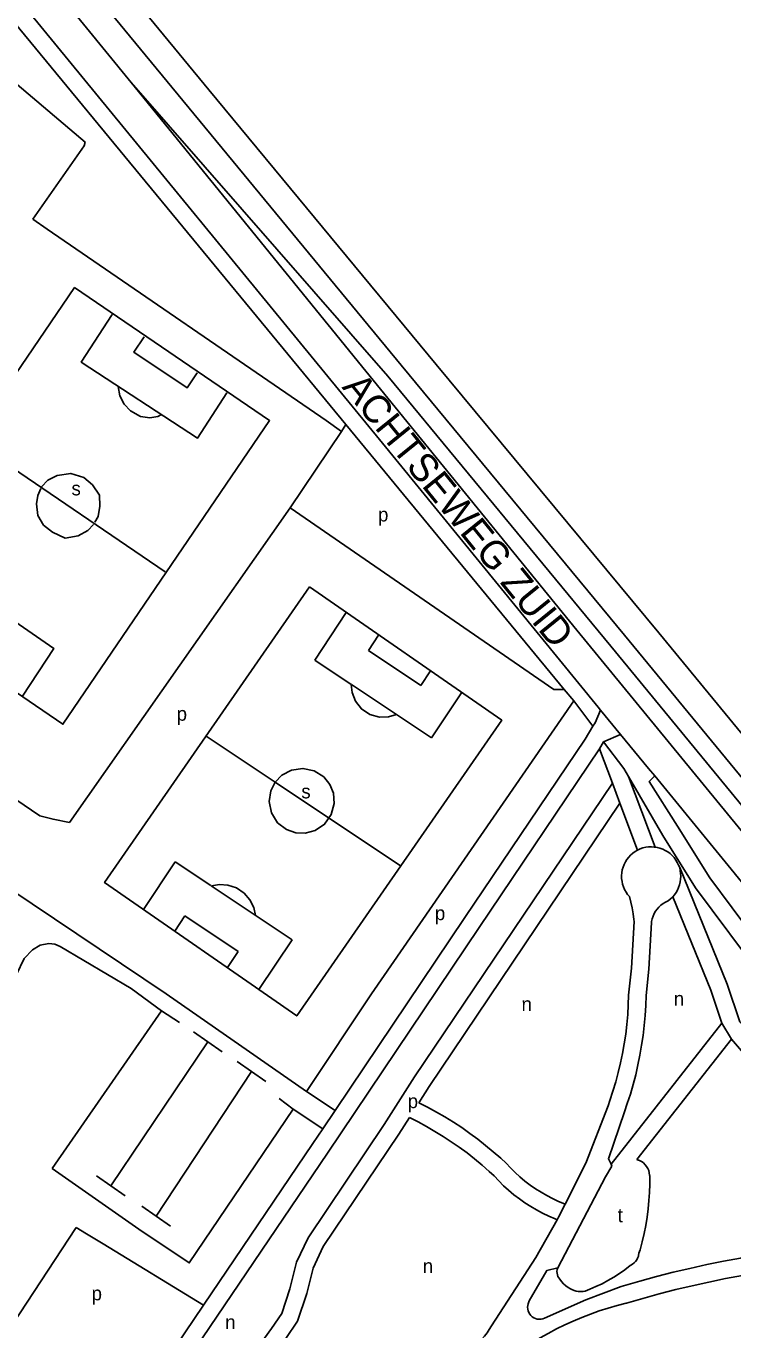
# Model space of a CAD drawing. Extents: x 157155 to 159285, y 385001 to 386651.
# Drawn here: x 158665.4 to 158867.8, y 385603.8 to 385977 of the extents above; entities that cross this region are included whole.
import ezdxf

# ---------------------------------------------------------------- set-up
doc = ezdxf.new("R2010")
doc.units = 0
for name, color, linetype in [('BLT_Basislijn', 7, 'Continuous'), ('BLT_Centroide', 7, 'Continuous'), ('BLT_Spoorlijn', 7, 'Continuous'), ('BLT_Straatnaam_hoofdweg', 7, 'Continuous'), ('BLT_Vlakafsluiter', 7, 'Continuous')]:
    doc.layers.add(name, color=color, linetype=linetype)

msp = doc.modelspace()

# ---------------------------------------------------------------- linework, layer by layer
at = {"layer": 'BLT_Basislijn'}
for p, q in [((158491.12, 386194.55), (158766.6, 385858.7)), ((158633.61, 386036.53), (158695.48, 385960.83)), ((158695.48, 385960.83), (158762.67, 385878.23)), ((158671.44, 385918.9), (158667.29, 385921.7)), ((158671.44, 385918.9), (158751.28, 385864.08)), ((158762.67, 385878.23), (158823.13, 385804.1)), ((158755.67, 385860.96), (158751.28, 385864.08)), ((158755.67, 385860.96), (158756.98, 385862.92)), ((158756.98, 385862.92), (158819.48, 385787.09)), ((158649.78, 385858.51), (158705.22, 385820.8)), ((158755.67, 385860.96), (158741.05, 385839.1)), ((158766.6, 385858.7), (158829.23, 385782.05)), ((158677.75, 385749.03), (158741.05, 385839.1)), ((158757.09, 385809.09), (158748.05, 385795.53)), ((158766.35, 385802.67), (158763.42, 385798.27)), ((158823.13, 385804.1), (158882.02, 385732.32)), ((158778.42, 385788.26), (158763.42, 385798.27)), ((158758.5, 385788.56), (158748.05, 385795.53)), ((158781.17, 385792.39), (158778.42, 385788.26)), ((158781.49, 385773.22), (158758.57, 385788.51)), ((158822.23, 385783.87), (158819.48, 385787.09)), ((158790.13, 385786.18), (158781.49, 385773.22)), ((158827.73, 385776.56), (158822.23, 385783.87)), ((158825.5, 385772.91), (158827.73, 385776.56)), ((158736.69, 385760.59), (158716.98, 385773.74)), ((158825.5, 385772.91), (158791.02, 385721.78)), ((158829.63, 385770.09), (158830.8, 385772.08)), ((158830.8, 385772.08), (158835.67, 385774.18)), ((158835.67, 385774.18), (158843.65, 385764.52)), ((158829.63, 385770.09), (158795.16, 385718.98)), ((158829.63, 385770.09), (158833.31, 385760.28)), ((158845.43, 385762.34), (158843.65, 385764.52)), ((158772.64, 385736.61), (158736.74, 385760.56)), ((158833.31, 385760.28), (158835.47, 385754.53)), ((158837.94, 385762.18), (158845.53, 385741.97)), ((158847.74, 385745.32), (158837.94, 385762.18)), ((158913.32, 385679.35), (158845.43, 385762.34)), ((158835.47, 385754.53), (158840.52, 385741.1)), ((158708.1, 385737.76), (158699.01, 385724.13)), ((158718.32, 385730.94), (158708.1, 385737.76)), ((158741.55, 385715.46), (158718.4, 385730.89)), ((158710.83, 385722.28), (158707.94, 385717.95)), ((158726.13, 385712.07), (158710.83, 385722.28)), ((158791.02, 385721.78), (158753.86, 385666.54)), ((158838.75, 385707.32), (158839.52, 385720.68)), ((158843.74, 385707.03), (158844.52, 385720.39)), ((158741.55, 385715.46), (158732.05, 385701.22)), ((158795.16, 385718.98), (158751.68, 385654.34)), ((158726.13, 385712.07), (158723.06, 385707.46)), ((158838.75, 385707.32), (158837.97, 385699.61)), ((158843.74, 385707.03), (158842.97, 385699.51)), ((158704.11, 385695.1), (158709.26, 385691.79)), ((158864.68, 385691.6), (158832.93, 385651.18)), ((158867.44, 385687.03), (158864.68, 385691.6)), ((158717.46, 385686.21), (158689.61, 385644.99)), ((158717.46, 385686.21), (158713.35, 385689.06)), ((158717.46, 385686.21), (158721.57, 385683.37)), ((158867.44, 385687.03), (158840.34, 385652.51)), ((158729.94, 385677.77), (158725.83, 385680.62)), ((158702.58, 385636.3), (158729.94, 385677.77)), ((158729.94, 385677.77), (158734.05, 385674.92)), ((158753.86, 385666.54), (158745.66, 385672.03)), ((158741.9, 385666.99), (158737.9, 385669.99)), ((158750.32, 385661.28), (158741.9, 385666.99)), ((158753.86, 385666.54), (158750.32, 385661.28)), ((158750.32, 385661.28), (158747.52, 385657.11)), ((158747.52, 385657.11), (158716.17, 385610.87)), ((158751.68, 385654.34), (158702.89, 385582.36)), ((158833.18, 385650.63), (158831.35, 385647.58)), ((158832.93, 385651.18), (158833.18, 385650.63)), ((158842.25, 385651.56), (158842.73, 385651.05)), ((158689.61, 385644.99), (158685.5, 385647.84)), ((158689.61, 385644.99), (158693.72, 385642.15)), ((158817.65, 385621.49), (158831.35, 385647.58)), ((158702.58, 385636.3), (158698.47, 385639.15)), ((158702.58, 385636.3), (158706.69, 385633.45)), ((158679.75, 385633.1), (158682.68, 385631.31)), ((158682.68, 385631.31), (158687.43, 385628.41)), ((158687.43, 385628.41), (158716.17, 385610.87)), ((158840.93, 385625.7), (158840.79, 385625.04)), ((158716.17, 385610.87), (158702.45, 385590.64))]:
    msp.add_line(p, q, dxfattribs=at)
for points in [[(158522.06, 386149.41), (158522.79, 386148.46), (158651.38, 385990.95), (158756.98, 385862.92)], [(158667.29, 385921.7), (158682.04, 385942.77), (158682.27, 385943.78), (158605.54, 386008.81)], [(158695.48, 385960.83), (158769, 385876.77), (158832.9, 385799.5)], [(158690.04, 385894.47), (158681.14, 385880.83), (158714.49, 385859.08), (158722.9, 385871.98)], [(158699.16, 385888.05), (158696.23, 385883.65), (158711.53, 385873.46), (158714.39, 385877.77)], [(158691.74, 385873.79), (158692.18, 385871.14), (158693.5, 385868.82), (158695.27, 385866.84), (158698.1, 385865.25), (158700.82, 385864.85), (158703.14, 385865.22), (158704.13, 385865.77)], [(158669.8, 385845.15), (158671.6, 385847.02), (158674.31, 385848.31), (158678.17, 385848.96), (158681.9, 385847.8), (158684.35, 385845.67), (158686.4, 385842.77), (158686.53, 385839.61), (158685.97, 385836.57), (158685.05, 385834.95)], [(158669.57, 385844.63), (158668.69, 385842.61), (158668.39, 385840.29), (158668.72, 385836.94), (158670.37, 385834.16), (158672.94, 385832.09), (158676.55, 385830.42), (158680.28, 385831.06), (158683.05, 385832.61), (158684.65, 385834.37)], [(158741.05, 385839.1), (158816.53, 385787.07), (158819.48, 385787.09)], [(158631.35, 385807.94), (158640.63, 385821.39), (158673.35, 385798.82), (158664.31, 385785.2)], [(158832.9, 385799.5), (158892.09, 385727.58), (158939.39, 385669.9)], [(158758.53, 385788.54), (158758.75, 385786.19), (158759.7, 385783.74), (158761.44, 385781.52), (158763.85, 385779.92), (158766.56, 385779.16), (158769.19, 385779.23), (158771.44, 385779.93)], [(158822.23, 385783.87), (158764.28, 385700), (158745.66, 385672.03)], [(158827.73, 385776.56), (158828.35, 385777.57), (158829.9, 385781.15)], [(158829.9, 385781.15), (158829.23, 385782.05)], [(158837.94, 385762.18), (158836.58, 385764.52), (158830.8, 385772.08)], [(158669.25, 385750.95), (158644.07, 385768.05), (158642.98, 385768.9), (158641.27, 385766.41)], [(158736.71, 385760.56), (158735.48, 385758.11), (158735.02, 385755.06), (158735.65, 385751.8), (158737.42, 385748.95), (158739.92, 385746.98), (158742.62, 385746.03), (158745.27, 385745.92), (158748.15, 385746.69), (158750.85, 385748.52), (158752.8, 385751.27), (158753.63, 385754.43), (158753.4, 385757.4), (158752.41, 385759.86), (158750.61, 385762.09), (158747.93, 385763.8), (158744.65, 385764.51), (158741.36, 385764.03), (158738.64, 385762.57), (158736.74, 385760.6)], [(158833.31, 385760.28), (158776.66, 385676.22), (158767.96, 385662.54), (158746.13, 385630.09), (158742.84, 385623.16), (158740.94, 385615.55), (158738.59, 385608.5), (158735.7, 385604.17), (158732.44, 385599.72), (158725.45, 385593.04)], [(158851.99, 385747.97), (158843.88, 385760.79), (158845.43, 385762.34)], [(158835.47, 385754.53), (158780.85, 385673.48), (158777.85, 385668.77)], [(158669.25, 385750.95), (158673.11, 385749.93), (158677.75, 385749.03)], [(158847.74, 385745.32), (158857.12, 385730.31), (158876.46, 385704.4), (158878.49, 385701.82)], [(158851.99, 385747.97), (158861.25, 385733.14), (158880.43, 385707.44), (158897.54, 385685.66), (158918.07, 385656.71), (158928.84, 385641.73)], [(158845.53, 385741.97), (158845.33, 385742), (158844.51, 385742.05), (158843.69, 385742.02), (158842.87, 385741.91), (158842.07, 385741.72), (158841.29, 385741.45), (158840.52, 385741.1)], [(158852.61, 385736.09), (158852.25, 385736.84), (158851.9, 385737.58), (158851.48, 385738.28), (158850.98, 385738.95), (158850.43, 385739.56), (158849.82, 385740.11), (158849.16, 385740.6), (158848.46, 385741.03), (158847.72, 385741.39), (158846.94, 385741.67), (158846.15, 385741.87), (158845.53, 385741.97)], [(158840.52, 385741.1), (158839.83, 385740.7), (158839.16, 385740.22), (158838.54, 385739.67), (158837.98, 385739.08), (158837.47, 385738.42), (158837.03, 385737.73), (158836.67, 385736.99), (158836.37, 385736.22), (158836.15, 385735.43), (158836.01, 385734.62), (158835.95, 385733.8), (158835.97, 385732.97), (158836.07, 385732.15), (158836.24, 385731.35), (158836.5, 385730.57), (158836.83, 385729.81), (158837.23, 385729.09), (158837.69, 385728.42), (158838.17, 385727.85)], [(158850.61, 385727.78), (158851.06, 385728.28), (158851.54, 385728.95), (158851.95, 385729.66), (158852.3, 385730.41), (158852.56, 385731.19), (158852.76, 385731.99), (158852.87, 385732.8), (158852.91, 385733.63), (158852.86, 385734.45), (158852.74, 385735.26), (158852.61, 385736.09)], [(158852.61, 385736.09), (158866.23, 385702.76), (158869.83, 385691.95), (158870.59, 385691.05)], [(158718.48, 385730.92), (158720.72, 385731.29), (158723.17, 385731.11), (158725.61, 385730.28), (158727.79, 385728.81), (158729.48, 385726.86), (158730.57, 385724.66), (158731.07, 385722.44)], [(158745.66, 385672.03), (158705.44, 385700), (158660.66, 385730.07)], [(158838.17, 385727.85), (158838.61, 385726.21), (158838.98, 385724.56), (158839.27, 385722.89), (158839.48, 385721.21), (158839.52, 385720.68)], [(158847.82, 385725.8), (158848.56, 385726.17), (158849.26, 385726.6), (158849.91, 385727.1), (158850.51, 385727.66), (158850.61, 385727.78)], [(158850.61, 385727.78), (158861.54, 385701.02), (158864.68, 385691.6)], [(158847.82, 385725.8), (158847.2, 385725.34), (158846.63, 385724.81), (158846.11, 385724.23), (158845.66, 385723.6), (158845.27, 385722.92), (158844.96, 385722.21), (158844.72, 385721.47), (158844.56, 385720.71), (158844.52, 385720.39)], [(158649.5, 385655.57), (158653.02, 385661.39), (158654.84, 385666.9), (158660.79, 385691.75), (158661.46, 385700.95), (158662.57, 385705.53), (158664.82, 385710.07), (158667.15, 385712.61), (158669.42, 385713.88), (158671.86, 385714.34), (158673.57, 385714.2), (158675.12, 385713.5)], [(158704.11, 385695.1), (158695.45, 385701.49), (158675.12, 385713.5)], [(158837.97, 385699.61), (158837.87, 385696.81), (158837.7, 385694.02), (158837.45, 385691.23), (158837.12, 385688.45), (158836.71, 385685.68), (158836.21, 385682.93), (158835.65, 385680.19), (158835, 385677.47), (158834.27, 385674.77), (158833.47, 385672.09), (158832.6, 385669.43), (158832.06, 385667.93)], [(158842.97, 385699.51), (158842.87, 385696.64), (158842.7, 385693.78), (158842.44, 385690.92), (158842.11, 385688.07), (158841.7, 385685.24), (158841.21, 385682.41), (158840.64, 385679.6), (158839.99, 385676.81), (158839.26, 385674.03), (158838.46, 385671.28), (158837.58, 385668.55), (158836.76, 385666.22)], [(158704.11, 385695.1), (158672.86, 385650.01)], [(158867.44, 385687.03), (158874.38, 385678.86), (158893.06, 385655.18), (158906.26, 385641.34), (158919.1, 385629.86)], [(158741.9, 385666.99), (158712.12, 385622.96), (158697.7, 385632.59), (158672.86, 385650.01)], [(158777.85, 385668.77), (158780.39, 385667.48), (158782.89, 385666.13), (158785.35, 385664.71), (158787.77, 385663.21), (158790.15, 385661.66), (158792.48, 385660.03), (158794.76, 385658.34), (158797, 385656.58), (158799.19, 385654.77), (158801.32, 385652.89), (158802.84, 385651.49)], [(158832.06, 385667.93), (158825.67, 385651.53), (158819.79, 385639.76)], [(158775.15, 385664.52), (158772.15, 385659.8), (158750.49, 385627.6), (158747.57, 385621.47), (158745.74, 385614.16), (158743.12, 385606.29), (158739.8, 385601.3), (158736.21, 385596.41), (158728.91, 385589.43)], [(158775.15, 385664.52), (158777.63, 385663.28), (158780.07, 385661.97), (158782.48, 385660.6), (158784.84, 385659.15), (158787.16, 385657.64), (158789.44, 385656.05), (158791.67, 385654.41), (158793.85, 385652.7), (158795.98, 385650.93), (158798.06, 385649.1), (158799.41, 385647.85)], [(158836.76, 385666.22), (158832.19, 385652.78), (158832.93, 385651.18)], [(158840.34, 385652.51), (158840.53, 385652.47), (158841.11, 385652.27), (158841.65, 385651.99), (158842.15, 385651.64), (158842.25, 385651.56)], [(158802.84, 385651.49), (158804.12, 385650.12), (158805.45, 385648.8), (158806.83, 385647.55), (158808.27, 385646.35), (158809.76, 385645.22), (158811.3, 385644.15), (158812.88, 385643.15), (158814.5, 385642.21), (158816.16, 385641.35), (158817.86, 385640.56), (158819.59, 385639.84), (158819.79, 385639.76)], [(158842.73, 385651.05), (158843.12, 385650.54), (158843.45, 385649.97), (158843.71, 385649.37), (158843.89, 385648.75), (158843.99, 385648.1), (158844.01, 385647.89)], [(158799.41, 385647.85), (158800.75, 385646.42), (158802.15, 385645.04), (158803.6, 385643.73), (158805.11, 385642.47), (158806.66, 385641.28), (158808.27, 385640.15), (158809.92, 385639.08), (158811.61, 385638.09), (158813.33, 385637.16), (158815.1, 385636.31), (158816.9, 385635.53), (158817.5, 385635.29)], [(158844.01, 385647.89), (158844.02, 385645.51), (158843.95, 385643.13), (158843.8, 385640.76), (158843.57, 385638.39), (158843.26, 385636.03), (158842.87, 385633.68), (158842.41, 385631.34), (158841.86, 385629.02), (158841.24, 385626.72), (158840.93, 385625.7)], [(158819.79, 385639.76), (158817.9, 385635.99), (158817.5, 385635.29)], [(158817.5, 385635.29), (158811.38, 385624.49), (158798.64, 385604.91)], [(158679.75, 385633.1), (158657.37, 385599.21), (158657.38, 385598.9), (158662.19, 385595.07)], [(158909.09, 385628.7), (158904.17, 385628.43), (158899.26, 385628.08), (158894.36, 385627.65), (158889.47, 385627.15), (158884.58, 385626.56), (158879.7, 385625.9), (158874.84, 385625.15), (158869.99, 385624.33), (158865.15, 385623.43), (158860.33, 385622.44), (158855.52, 385621.38), (158850.73, 385620.25), (158845.96, 385619.03), (158841.21, 385617.74), (158836.49, 385616.37), (158835.79, 385616.16)], [(158826.83, 385615.4), (158828.6, 385616.15), (158830.34, 385616.98), (158832.04, 385617.88), (158833.7, 385618.85), (158835.32, 385619.89), (158836.9, 385620.99), (158838.43, 385622.16), (158838.56, 385622.27)], [(158909.32, 385623.7), (158904.45, 385623.44), (158899.58, 385623.09), (158894.71, 385622.67), (158889.86, 385622.16), (158885.02, 385621.58), (158880.18, 385620.91), (158875.36, 385620.17), (158870.55, 385619.35), (158865.75, 385618.45), (158860.97, 385617.47), (158856.2, 385616.41), (158851.46, 385615.28), (158846.73, 385614.06), (158842.02, 385612.77), (158837.34, 385611.41), (158837.23, 385611.37)], [(158838.56, 385622.27), (158839.06, 385622.56), (158839.52, 385622.93), (158839.93, 385623.35), (158840.27, 385623.82), (158840.55, 385624.34), (158840.75, 385624.88), (158840.79, 385625.04)], [(158809.51, 385612.06), (158814.49, 385620.76), (158817.65, 385621.49)], [(158817.65, 385621.49), (158817.5, 385621.01), (158817.44, 385620.52), (158817.45, 385620.03), (158817.55, 385619.54), (158817.71, 385619.07), (158817.96, 385618.64), (158818.28, 385618.24)], [(158835.79, 385616.16), (158825.67, 385612.37), (158813.86, 385607.08)], [(158818.28, 385618.24), (158818.77, 385617.59), (158819.33, 385616.98), (158819.94, 385616.42), (158820.61, 385615.93), (158821.32, 385615.51), (158821.71, 385615.31)], [(158821.71, 385615.31), (158822.32, 385615.05), (158822.95, 385614.86), (158823.6, 385614.74), (158824.25, 385614.71), (158824.91, 385614.76), (158825.56, 385614.89), (158826.18, 385615.09), (158826.83, 385615.4)], [(158837.23, 385611.37), (158834.65, 385610.72), (158832.09, 385609.99), (158829.55, 385609.18), (158827.04, 385608.29), (158824.55, 385607.33), (158822.1, 385606.3), (158819.67, 385605.19), (158817.29, 385604.02), (158814.93, 385602.77), (158812.62, 385601.45), (158810.35, 385600.06), (158808.12, 385598.6), (158805.94, 385597.08), (158803.92, 385595.58)], [(158813.86, 385607.08), (158813.37, 385606.91), (158812.85, 385606.81), (158812.32, 385606.8), (158811.8, 385606.86), (158811.29, 385607), (158810.82, 385607.22), (158810.37, 385607.51), (158809.98, 385607.86), (158809.65, 385608.26), (158809.38, 385608.71), (158809.18, 385609.2), (158809.06, 385609.71), (158809.01, 385610.24), (158809.05, 385610.76), (158809.16, 385611.27), (158809.36, 385611.76), (158809.51, 385612.06)], [(158798.64, 385604.91), (158798.06, 385603.89), (158797.41, 385602.92), (158796.69, 385602), (158795.92, 385601.12), (158795.08, 385600.31), (158794.2, 385599.55), (158793.26, 385598.85), (158792.27, 385598.22), (158791.25, 385597.66), (158790.19, 385597.17), (158789.1, 385596.75), (158787.98, 385596.41), (158787.14, 385596.2)]]:
    msp.add_lwpolyline(points, dxfattribs=at)
for points in [[(158620, 385815.23), (158675.89, 385777.15), (158735.13, 385864.09), (158679.25, 385902.17)], [(158746.54, 385816.46), (158687.85, 385731.82), (158742.91, 385693.64), (158801.6, 385778.29)]]:
    msp.add_lwpolyline(points, close=True, dxfattribs=at)
at = {"layer": 'BLT_Spoorlijn'}
for points in [[(158641.91, 386038.56), (158705.82, 385961.14)], [(158653.19, 386037), (158717.72, 385958.79)], [(158705.82, 385961.14), (158772.85, 385879.96)], [(158717.72, 385958.79), (158782.87, 385880.11)], [(158772.85, 385879.96), (158836.75, 385802.69)], [(158782.87, 385880.11), (158846.62, 385803.32)], [(158836.75, 385802.69), (158895.96, 385730.75)], [(158846.62, 385803.32), (158905.82, 385731.38)]]:
    msp.add_lwpolyline(points, dxfattribs=at)
at = {"layer": 'BLT_Vlakafsluiter'}
msp.add_line((158829.9, 385781.15), (158835.67, 385774.18), dxfattribs=at)

# ---------------------------------------------------------------- texts
at = {"layer": 'BLT_Centroide'}
for s, p in [('s', (158678.37, 385842.66)), ('p', (158766.17, 385835.19)), ('p', (158708.49, 385778.15)), ('s', (158744.21, 385755.92)), ('p', (158782.47, 385721.06)), ('n', (158807.29, 385695.04)), ('n', (158850.89, 385696.57)), ('p', (158774.67, 385667.25)), ('t', (158834.83, 385634.59)), ('n', (158778.99, 385620.05)), ('p', (158684.13, 385612.23)), ('n', (158722.39, 385603.98))]:
    msp.add_text(s, height=4, dxfattribs=at).set_placement(p)
at = {"layer": 'BLT_Straatnaam_hoofdweg'}
msp.add_text('ACHTSEWEG ZUID', height=8, rotation=309.0181, dxfattribs=at).set_placement((158755.65, 385873.57))

doc.saveas('drawing.dxf')
